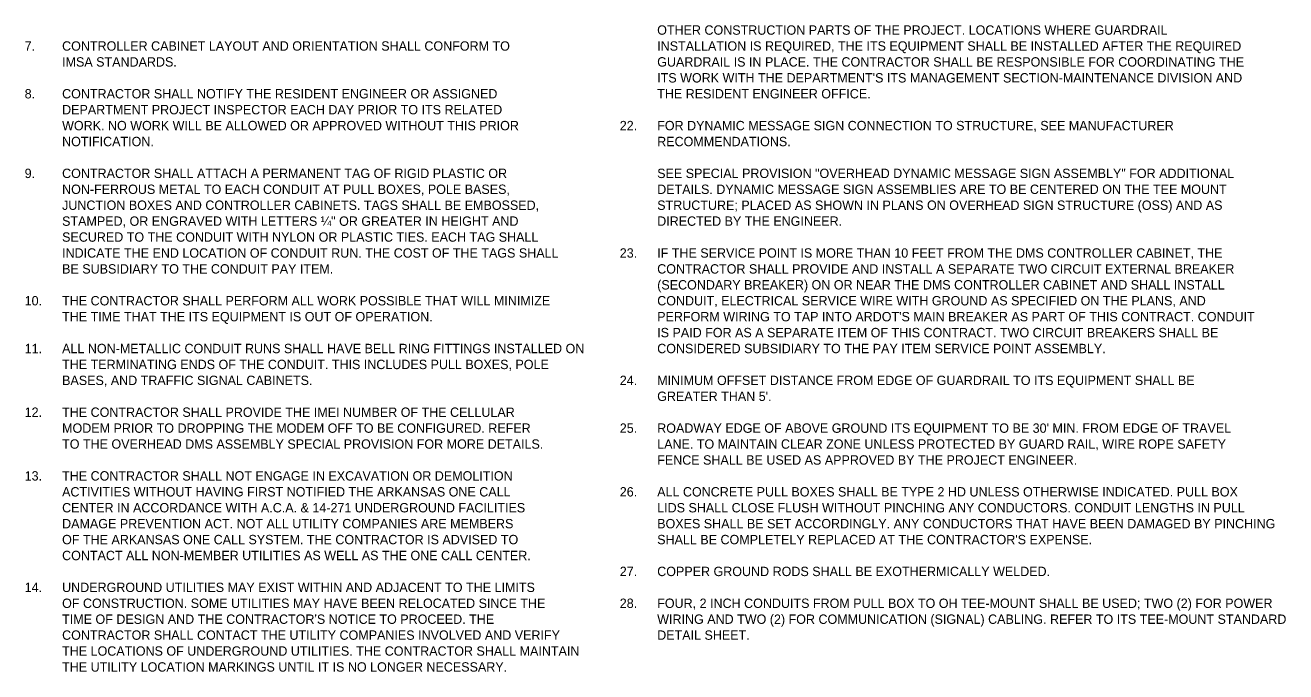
# Model space of a CAD drawing. Extents: x 118 to 1642, y 42 to 1033.
# Drawn here: x 118 to 1047, y 61 to 537 of the extents above; entities that cross this region are included whole.
import ezdxf

# ---------------------------------------------------------------- set-up
doc = ezdxf.new("R2010")
doc.units = 0
doc.layers.add('C-ANNO-TEXT', color=7, linetype='Continuous')

msp = doc.modelspace()

# ---------------------------------------------------------------- texts
at = {"layer": 'C-ANNO-TEXT'}
for s, height, p in [('OTHER CONSTRUCTION PARTS OF THE PROJECT. LOCATIONS WHERE GUARDRAIL ', 6.8991, (583.7, 529.87)), ('7.', 6.899, (117.38, 518.14)), ('CONTROLLER CABINET LAYOUT AND ORIENTATION SHALL CONFORM TO ', 6.8991, (144.98, 518.14)), ('INSTALLATION IS REQUIRED, THE ITS EQUIPMENT SHALL BE INSTALLED AFTER THE REQUIRED ', 6.8991, (583.7, 518.14)), ('IMSA STANDARDS.', 6.8991, (144.98, 506.41)), ('GUARDRAIL IS IN PLACE. THE CONTRACTOR SHALL BE RESPONSIBLE FOR COORDINATING THE ', 6.8991, (583.7, 506.41)), ("ITS WORK WITH THE DEPARTMENT'S ITS MANAGEMENT SECTION-MAINTENANCE DIVISION AND ", 6.8991, (583.7, 494.69)), ('8.', 6.899, (117.38, 482.96)), ('CONTRACTOR SHALL NOTIFY THE RESIDENT ENGINEER OR ASSIGNED ', 6.8991, (144.98, 482.96)), ('THE RESIDENT ENGINEER OFFICE. ', 6.8991, (583.7, 482.96)), ('DEPARTMENT PROJECT INSPECTOR EACH DAY PRIOR TO ITS RELATED ', 6.8991, (144.98, 471.23)), ('WORK. NO WORK WILL BE ALLOWED OR APPROVED WITHOUT THIS PRIOR ', 6.8991, (144.98, 459.5)), ('22.', 6.899, (556.11, 459.5)), ('FOR DYNAMIC MESSAGE SIGN CONNECTION TO STRUCTURE, SEE MANUFACTURER ', 6.8991, (583.7, 459.5)), ('NOTIFICATION.', 6.8991, (144.98, 447.77)), ('RECOMMENDATIONS. ', 6.8991, (583.7, 447.77)), ('9.', 6.899, (117.38, 424.31)), ('CONTRACTOR SHALL ATTACH A PERMANENT TAG OF RIGID PLASTIC OR ', 6.8991, (144.98, 424.31)), ('SEE SPECIAL PROVISION "OVERHEAD DYNAMIC MESSAGE SIGN ASSEMBLY" FOR ADDITIONAL ', 6.8991, (583.7, 424.31)), ('NON-FERROUS METAL TO EACH CONDUIT AT PULL BOXES, POLE BASES, ', 6.8991, (144.98, 412.59)), ('DETAILS. DYNAMIC MESSAGE SIGN ASSEMBLIES ARE TO BE CENTERED ON THE TEE MOUNT ', 6.8991, (583.7, 412.59)), ('JUNCTION BOXES AND CONTROLLER CABINETS. TAGS SHALL BE EMBOSSED, ', 6.8991, (144.98, 400.86)), ('STRUCTURE; PLACED AS SHOWN IN PLANS ON OVERHEAD SIGN STRUCTURE (OSS) AND AS ', 6.8991, (583.7, 400.86)), ('STAMPED, OR ENGRAVED WITH LETTERS ¼" OR GREATER IN HEIGHT AND ', 6.8991, (144.98, 389.13)), ('DIRECTED BY THE ENGINEER.', 6.8991, (583.7, 389.13)), ('SECURED TO THE CONDUIT WITH NYLON OR PLASTIC TIES. EACH TAG SHALL ', 6.8991, (144.98, 377.4)), ('INDICATE THE END LOCATION OF CONDUIT RUN. THE COST OF THE TAGS SHALL ', 6.8991, (144.98, 365.67)), ('23.', 6.899, (556.11, 365.67)), ('IF THE SERVICE POINT IS MORE THAN 10 FEET FROM THE DMS CONTROLLER CABINET, THE ', 6.8991, (583.7, 365.67)), ('BE SUBSIDIARY TO THE CONDUIT PAY ITEM.', 6.8991, (144.98, 353.94)), ('CONTRACTOR SHALL PROVIDE AND INSTALL A SEPARATE TWO CIRCUIT EXTERNAL BREAKER ', 6.8991, (583.7, 353.94)), ('(SECONDARY BREAKER) ON OR NEAR THE DMS CONTROLLER CABINET AND SHALL INSTALL ', 6.8991, (583.7, 342.21)), ('10.', 6.899, (117.38, 330.49)), ('THE CONTRACTOR SHALL PERFORM ALL WORK POSSIBLE THAT WILL MINIMIZE ', 6.8991, (144.98, 330.49)), ('CONDUIT, ELECTRICAL SERVICE WIRE WITH GROUND AS SPECIFIED ON THE PLANS, AND ', 6.8991, (583.7, 330.49)), ('THE TIME THAT THE ITS EQUIPMENT IS OUT OF OPERATION.', 6.8991, (144.98, 318.76)), ("PERFORM WIRING TO TAP INTO ARDOT'S MAIN BREAKER AS PART OF THIS CONTRACT. CONDUIT ", 6.8991, (583.7, 318.76)), ('IS PAID FOR AS A SEPARATE ITEM OF THIS CONTRACT. TWO CIRCUIT BREAKERS SHALL BE ', 6.8991, (583.7, 307.03)), ('11.', 6.899, (117.38, 295.3)), ('ALL NON-METALLIC CONDUIT RUNS SHALL HAVE BELL RING FITTINGS INSTALLED ON ', 6.8991, (144.98, 295.3)), ('CONSIDERED SUBSIDIARY TO THE PAY ITEM SERVICE POINT ASSEMBLY.', 6.8991, (583.7, 295.3)), ('THE TERMINATING ENDS OF THE CONDUIT. THIS INCLUDES PULL BOXES, POLE ', 6.8991, (144.98, 283.57)), ('BASES, AND TRAFFIC SIGNAL CABINETS. ', 6.8991, (144.98, 271.84)), ('24.', 6.899, (556.11, 271.84)), ('MINIMUM OFFSET DISTANCE FROM EDGE OF GUARDRAIL TO ITS EQUIPMENT SHALL BE', 6.8991, (583.7, 271.84)), ("GREATER THAN 5'.", 6.8991, (583.7, 260.11)), ('12.', 6.899, (117.38, 248.39)), ('THE CONTRACTOR SHALL PROVIDE THE IMEI NUMBER OF THE CELLULAR ', 6.8991, (144.98, 248.39)), ('MODEM PRIOR TO DROPPING THE MODEM OFF TO BE CONFIGURED. REFER ', 6.8991, (144.98, 236.66)), ('25.', 6.899, (556.11, 236.66)), ("ROADWAY EDGE OF ABOVE GROUND ITS EQUIPMENT TO BE 30' MIN. FROM EDGE OF TRAVEL ", 6.8991, (583.7, 236.66)), ('TO THE OVERHEAD DMS ASSEMBLY SPECIAL PROVISION FOR MORE DETAILS.', 6.8991, (144.98, 224.93)), ('LANE. TO MAINTAIN CLEAR ZONE UNLESS PROTECTED BY GUARD RAIL, WIRE ROPE SAFETY ', 6.8991, (583.7, 224.93)), ('FENCE SHALL BE USED AS APPROVED BY THE PROJECT ENGINEER.', 6.8991, (583.7, 213.2)), ('13.', 6.899, (117.38, 201.47)), ('THE CONTRACTOR SHALL NOT ENGAGE IN EXCAVATION OR DEMOLITION ', 6.8991, (144.98, 201.47)), ('ACTIVITIES WITHOUT HAVING FIRST NOTIFIED THE ARKANSAS ONE CALL ', 6.8991, (144.98, 189.74)), ('26.', 6.899, (556.11, 189.74)), ('ALL CONCRETE PULL BOXES SHALL BE TYPE 2 HD UNLESS OTHERWISE INDICATED. PULL BOX ', 6.8991, (583.7, 189.74)), ('CENTER IN ACCORDANCE WITH A.C.A. & 14-271 UNDERGROUND FACILITIES ', 6.8991, (144.98, 178.02)), ('LIDS SHALL CLOSE FLUSH WITHOUT PINCHING ANY CONDUCTORS. CONDUIT LENGTHS IN PULL ', 6.8991, (583.7, 178.02)), ('DAMAGE PREVENTION ACT. NOT ALL UTILITY COMPANIES ARE MEMBERS ', 6.8991, (144.98, 166.29)), ('BOXES SHALL BE SET ACCORDINGLY. ANY CONDUCTORS THAT HAVE BEEN DAMAGED BY PINCHING ', 6.8991, (583.7, 166.29)), ('OF THE ARKANSAS ONE CALL SYSTEM. THE CONTRACTOR IS ADVISED TO ', 6.8991, (144.98, 154.56)), ("SHALL BE COMPLETELY REPLACED AT THE CONTRACTOR'S EXPENSE. ", 6.8991, (583.7, 154.56)), ('CONTACT ALL NON-MEMBER UTILITIES AS WELL AS THE ONE CALL CENTER. ', 6.8991, (144.98, 142.83)), ('27.', 6.899, (556.11, 131.1)), ('COPPER GROUND RODS SHALL BE EXOTHERMICALLY WELDED.', 6.8991, (583.7, 131.1)), ('14.', 6.899, (117.38, 119.37)), ('UNDERGROUND UTILITIES MAY EXIST WITHIN AND ADJACENT TO THE LIMITS ', 6.8991, (144.98, 119.37)), ('OF CONSTRUCTION. SOME UTILITIES MAY HAVE BEEN RELOCATED SINCE THE ', 6.8991, (144.98, 107.64)), ('28.', 6.899, (556.11, 107.64)), ('FOUR, 2 INCH CONDUITS FROM PULL BOX TO OH TEE-MOUNT SHALL BE USED; TWO (2) FOR POWER ', 6.8991, (583.7, 107.64)), ("TIME OF DESIGN AND THE CONTRACTOR'S NOTICE TO PROCEED. THE ", 6.8991, (144.98, 95.92)), ('WIRING AND TWO (2) FOR COMMUNICATION (SIGNAL) CABLING. REFER TO ITS TEE-MOUNT STANDARD ', 6.8991, (583.7, 95.92)), ('CONTRACTOR SHALL CONTACT THE UTILITY COMPANIES INVOLVED AND VERIFY ', 6.8991, (144.98, 84.19)), ('DETAIL SHEET.', 6.8991, (583.7, 84.19)), ('THE LOCATIONS OF UNDERGROUND UTILITIES. THE CONTRACTOR SHALL MAINTAIN ', 6.8991, (144.98, 72.46)), ('THE UTILITY LOCATION MARKINGS UNTIL IT IS NO LONGER NECESSARY. ', 6.8991, (144.98, 60.73))]:
    msp.add_text(s, height=height, rotation=0, dxfattribs=at).set_placement(p)

doc.saveas('drawing.dxf')
